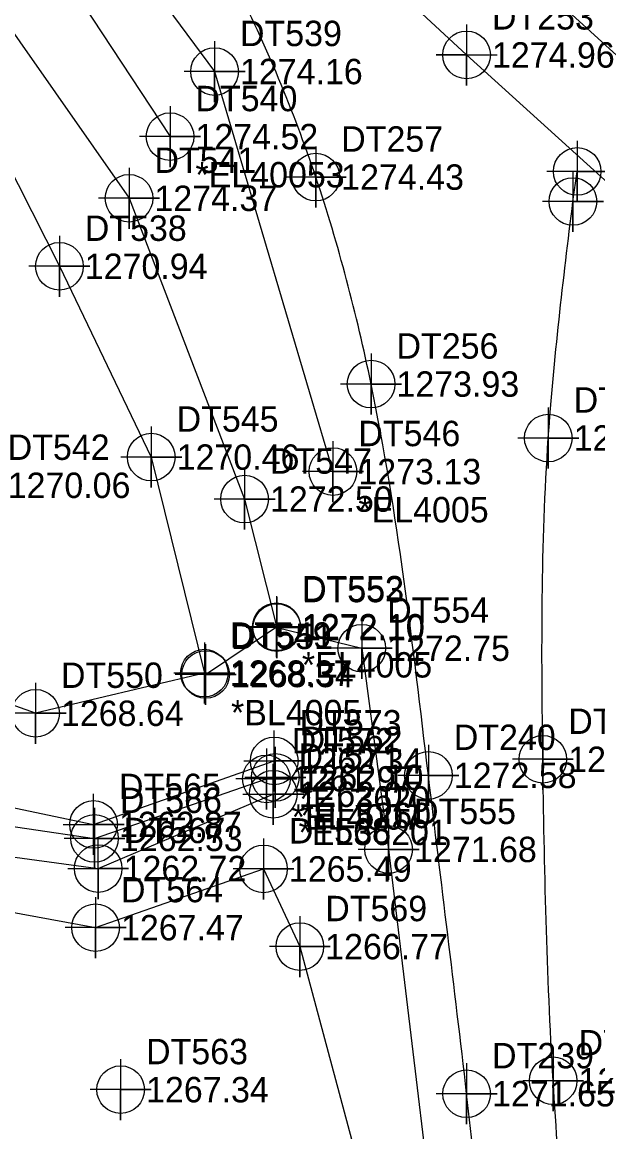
# Model space of a CAD drawing. Extents: x 1391270 to 1392151, y 960049 to 960667.
# Drawn here: x 1391450.5 to 1391507.1, y 960335.6 to 960444.8 of the extents above; entities that cross this region are included whole.
import ezdxf

# ---------------------------------------------------------------- set-up
doc = ezdxf.new("R2010")
doc.units = 0
for name, color, linetype in [('Exist DTM Breakline', 7, 'Continuous'), ('Exist DTM Breakline Cogo Comment', 7, 'Continuous'), ('Exist DTM Breakline Cogo Elevation', 7, 'Continuous'), ('Exist DTM Breakline Cogo Number', 7, 'Continuous'), ('Exist DTM Breakline Cogo Point CELL', 7, 'Continuous'), ('Exist DTM Breakline Underwater', 7, 'Continuous'), ('Exist DTM Breakline Underwater Cogo Comment', 7, 'Continuous'), ('Exist DTM Breakline Underwater Cogo Elevation', 7, 'Continuous'), ('Exist DTM Breakline Underwater Cogo Number', 7, 'Continuous'), ('Exist DTM Breakline Underwater Cogo Point CELL', 7, 'Continuous'), ('Exist DTM Crownline', 7, 'Continuous'), ('Exist DTM Crownline Cogo Elevation', 7, 'Continuous'), ('Exist DTM Crownline Cogo Number', 7, 'Continuous'), ('Exist DTM Crownline Cogo Point CELL', 7, 'Continuous'), ('Exist DTM Regular Point CELL', 7, 'Continuous'), ('Exist DTM Regular Point Cogo Elevation', 7, 'Continuous'), ('Exist DTM Regular Point Cogo Number', 7, 'Continuous'), ('Exist Hydro Stream or Body of Water', 7, 'Continuous'), ('Exist Hydro Stream or Body of Water Cogo Comment', 7, 'Continuous'), ('Exist Hydro Stream or Body of Water Cogo Elevation', 7, 'Continuous'), ('Exist Hydro Stream or Body of Water Cogo Number', 7, 'Continuous'), ('Exist Hydro Stream or Body of Water Cogo Point CELL', 7, 'Continuous'), ('Exist Roads EOP', 7, 'Continuous'), ('Exist Roads EOP Cogo Elevation', 7, 'Continuous'), ('Exist Roads EOP Cogo Number', 7, 'Continuous'), ('Exist Roads EOP Cogo Point CELL', 7, 'Continuous'), ('Exist Roads EOT', 7, 'Continuous'), ('Exist Roads EOT Cogo Elevation', 7, 'Continuous'), ('Exist Roads EOT Cogo Number', 7, 'Continuous'), ('Exist Roads EOT Cogo Point CELL', 7, 'Continuous'), ('Exist Structure Minor Pipes CMP 60 Inch Cogo Comment', 7, 'Continuous'), ('Exist Structure Minor Pipes CMP 60 Inch Cogo Elevation', 7, 'Continuous'), ('Exist Structure Minor Pipes CMP 60 Inch Cogo Number', 7, 'Continuous'), ('Exist Structure Minor Pipes CMP 60 Inch Cogo Point CELL', 7, 'Continuous')]:
    doc.layers.add(name, color=color, linetype=linetype)

msp = doc.modelspace()

# ---------------------------------------------------------------- linework, layer by layer
at = {"layer": 'Exist DTM Breakline'}
msp.add_line((1391468.506, 960380.602), (1391475.48, 960385.301), dxfattribs=at)
for points in [[(1391324.233, 960586.705), (1391339.042, 960571.952), (1391361.254, 960553.328), (1391397.359, 960520.55), (1391431.984, 960487.022), (1391447.858, 960468.977), (1391469.387, 960439.951), (1391481.042, 960400.574)], [(1391316.128, 960578.463), (1391335.373, 960567.825), (1391355.688, 960547.259), (1391385.482, 960507.01), (1391423.359, 960476.875), (1391439.432, 960458.285), (1391460.969, 960427.473), (1391472.339, 960397.865), (1391475.509, 960385.212), (1391483.88, 960383.187), (1391486.523, 960363.38), (1391492.773, 960311.276)], [(1391303.798, 960568.714), (1391337.195, 960549.348), (1391355.915, 960524.922), (1391369.834, 960491.808), (1391382.04, 960457.756), (1391381.24, 960442.404), (1391402.896, 960452.148), (1391420.738, 960472.565), (1391439.191, 960450.264), (1391454.114, 960420.78), (1391463.153, 960401.998), (1391468.38, 960380.734), (1391451.764, 960376.78), (1391432.731, 960383.561)], [(1391374.906, 960532.045), (1391391.307, 960515.216), (1391429.365, 960483.152), (1391444, 960465.435), (1391465.005, 960433.545)], [(1391421.76, 960362.297), (1391457.674, 960355.681), (1391474.205, 960361.463), (1391477.78, 960353.817), (1391489.16, 960311.358)]]:
    msp.add_lwpolyline(points, dxfattribs=at)
at = {"layer": 'Exist DTM Breakline Cogo Point CELL'}
for points in [[(1391469.387, 960442.951), (1391469.387, 960436.951), (1391469.387, 960439.951), (1391472.387, 960439.951), (1391466.387, 960439.951)], [(1391465.005, 960436.545), (1391465.005, 960430.545), (1391465.005, 960433.545), (1391468.005, 960433.545), (1391462.005, 960433.545)], [(1391460.969, 960430.473), (1391460.969, 960424.473), (1391460.969, 960427.473), (1391463.969, 960427.473), (1391457.969, 960427.473)], [(1391454.114, 960423.78), (1391454.114, 960417.78), (1391454.114, 960420.78), (1391457.114, 960420.78), (1391451.114, 960420.78)], [(1391463.153, 960404.998), (1391463.153, 960398.998), (1391463.153, 960401.998), (1391466.153, 960401.998), (1391460.153, 960401.998)], [(1391481.042, 960403.574), (1391481.042, 960397.574), (1391481.042, 960400.574), (1391484.042, 960400.574), (1391478.042, 960400.574)], [(1391472.339, 960400.865), (1391472.339, 960394.865), (1391472.339, 960397.865), (1391475.339, 960397.865), (1391469.339, 960397.865)], [(1391475.48, 960388.301), (1391475.48, 960382.301), (1391475.48, 960385.301), (1391478.48, 960385.301), (1391472.48, 960385.301)], [(1391475.509, 960388.212), (1391475.509, 960382.212), (1391475.509, 960385.212), (1391478.509, 960385.212), (1391472.509, 960385.212)], [(1391483.88, 960386.187), (1391483.88, 960380.187), (1391483.88, 960383.187), (1391486.88, 960383.187), (1391480.88, 960383.187)], [(1391468.38, 960383.734), (1391468.38, 960377.734), (1391468.38, 960380.734), (1391471.38, 960380.734), (1391465.38, 960380.734)], [(1391468.506, 960383.602), (1391468.506, 960377.602), (1391468.506, 960380.602), (1391471.506, 960380.602), (1391465.506, 960380.602)], [(1391451.764, 960379.78), (1391451.764, 960373.78), (1391451.764, 960376.78), (1391454.764, 960376.78), (1391448.764, 960376.78)], [(1391486.523, 960366.38), (1391486.523, 960360.38), (1391486.523, 960363.38), (1391489.523, 960363.38), (1391483.523, 960363.38)], [(1391474.205, 960364.463), (1391474.205, 960358.463), (1391474.205, 960361.463), (1391477.205, 960361.463), (1391471.205, 960361.463)], [(1391457.674, 960358.681), (1391457.674, 960352.681), (1391457.674, 960355.681), (1391460.674, 960355.681), (1391454.674, 960355.681)], [(1391477.78, 960356.817), (1391477.78, 960350.817), (1391477.78, 960353.817), (1391480.78, 960353.817), (1391474.78, 960353.817)]]:
    msp.add_lwpolyline(points, dxfattribs=at)
for centre in [(1391469.387, 960439.951), (1391465.005, 960433.545), (1391460.969, 960427.473), (1391454.114, 960420.78), (1391463.153, 960401.998), (1391481.042, 960400.574), (1391472.339, 960397.865), (1391475.48, 960385.301), (1391475.509, 960385.212), (1391483.88, 960383.187), (1391468.38, 960380.734), (1391468.506, 960380.602), (1391451.764, 960376.78), (1391486.523, 960363.38), (1391474.205, 960361.463), (1391457.674, 960355.681), (1391477.78, 960353.817)]:
    msp.add_circle(centre, 2.344, dxfattribs=at)
at = {"layer": 'Exist DTM Breakline Underwater'}
msp.add_lwpolyline([(1391424.242, 960369.381), (1391457.57, 960364.468), (1391474.484, 960370.327)], dxfattribs=at)
at = {"layer": 'Exist DTM Breakline Underwater Cogo Point CELL'}
for points in [[(1391474.484, 960373.327), (1391474.484, 960367.327), (1391474.484, 960370.327), (1391477.484, 960370.327), (1391471.484, 960370.327)], [(1391457.57, 960367.468), (1391457.57, 960361.468), (1391457.57, 960364.468), (1391460.57, 960364.468), (1391454.57, 960364.468)]]:
    msp.add_lwpolyline(points, dxfattribs=at)
for centre in [(1391474.484, 960370.327), (1391457.57, 960364.468)]:
    msp.add_circle(centre, 2.344, dxfattribs=at)
at = {"layer": 'Exist DTM Crownline'}
msp.add_line((1391504.663, 960427.16), (1391505.082, 960430.114), dxfattribs=at)
msp.add_lwpolyline([(1391336.775, 960598.787), (1391373.255, 960565.397), (1391410.328, 960531.742), (1391446.425, 960498.79), (1391483.147, 960465.095), (1391520.03, 960431.473), (1391553.996, 960400.745), (1391556.572, 960398.448)], dxfattribs=at)
msp.add_spline([(1391505.005, 960312.528), (1391502.717, 960340.608), (1391501.701, 960372.252), (1391502.238, 960403.877), (1391504.663, 960427.16)], degree=3, dxfattribs=at)
at = {"layer": 'Exist DTM Crownline Cogo Point CELL'}
for points in [[(1391505.082, 960433.114), (1391505.082, 960427.114), (1391505.082, 960430.114), (1391508.082, 960430.114), (1391502.082, 960430.114)], [(1391504.663, 960430.16), (1391504.663, 960424.16), (1391504.663, 960427.16), (1391507.663, 960427.16), (1391501.663, 960427.16)], [(1391502.238, 960406.877), (1391502.238, 960400.877), (1391502.238, 960403.877), (1391505.238, 960403.877), (1391499.238, 960403.877)], [(1391501.701, 960375.252), (1391501.701, 960369.252), (1391501.701, 960372.252), (1391504.701, 960372.252), (1391498.701, 960372.252)], [(1391502.717, 960343.608), (1391502.717, 960337.608), (1391502.717, 960340.608), (1391505.717, 960340.608), (1391499.717, 960340.608)]]:
    msp.add_lwpolyline(points, dxfattribs=at)
for centre in [(1391505.082, 960430.114), (1391504.663, 960427.16), (1391502.238, 960403.877), (1391501.701, 960372.252), (1391502.717, 960340.608)]:
    msp.add_circle(centre, 2.344, dxfattribs=at)
at = {"layer": 'Exist DTM Regular Point CELL'}
msp.add_lwpolyline([(1391460.143, 960342.737), (1391460.143, 960336.737), (1391460.143, 960339.737), (1391463.143, 960339.737), (1391457.143, 960339.737)], dxfattribs=at)
msp.add_circle((1391460.143, 960339.737), 2.344, dxfattribs=at)
at = {"layer": 'Exist Hydro Stream or Body of Water'}
for points in [[(1391424.856, 960372.683), (1391457.478, 960365.839), (1391475.256, 960372.097)], [(1391423.375, 960366.208), (1391457.93, 960361.502), (1391475.159, 960368.812)]]:
    msp.add_lwpolyline(points, dxfattribs=at)
at = {"layer": 'Exist Hydro Stream or Body of Water Cogo Point CELL'}
for points in [[(1391472.256, 960372.097), (1391478.256, 960372.097), (1391475.256, 960372.097), (1391475.256, 960369.097), (1391475.256, 960375.097)], [(1391472.159, 960368.812), (1391478.159, 960368.812), (1391475.159, 960368.812), (1391475.159, 960365.812), (1391475.159, 960371.812)], [(1391454.478, 960365.839), (1391460.478, 960365.839), (1391457.478, 960365.839), (1391457.478, 960362.839), (1391457.478, 960368.839)], [(1391454.93, 960361.502), (1391460.93, 960361.502), (1391457.93, 960361.502), (1391457.93, 960358.502), (1391457.93, 960364.502)]]:
    msp.add_lwpolyline(points, dxfattribs=at)
for centre in [(1391475.256, 960372.097), (1391475.159, 960368.812), (1391457.478, 960365.839), (1391457.93, 960361.502)]:
    msp.add_circle(centre, 2.344, dxfattribs=at)
at = {"layer": 'Exist Roads EOP'}
for points in [[(1391558.507, 960409.653), (1391527.113, 960438.384), (1391489.556, 960472.216), (1391453.007, 960506.097), (1391416.783, 960539.246), (1391379.565, 960572.597), (1391343.959, 960605.485)], [(1391497.16, 960311.857), (1391494.199, 960339.333), (1391490.437, 960370.67), (1391484.795, 960409.189), (1391479.352, 960429.561), (1391471.345, 960448.702), (1391460.843, 960466.873), (1391449.093, 960483.056), (1391440.139, 960491.898), (1391403.899, 960524.912), (1391366.94, 960558.603)]]:
    msp.add_spline(points, degree=3, dxfattribs=at)
at = {"layer": 'Exist Roads EOP Cogo Point CELL'}
for points in [[(1391479.352, 960432.561), (1391479.352, 960426.561), (1391479.352, 960429.561), (1391482.352, 960429.561), (1391476.352, 960429.561)], [(1391484.795, 960412.189), (1391484.795, 960406.189), (1391484.795, 960409.189), (1391487.795, 960409.189), (1391481.795, 960409.189)], [(1391490.437, 960373.67), (1391490.437, 960367.67), (1391490.437, 960370.67), (1391493.437, 960370.67), (1391487.437, 960370.67)], [(1391494.199, 960342.333), (1391494.199, 960336.333), (1391494.199, 960339.333), (1391497.199, 960339.333), (1391491.199, 960339.333)]]:
    msp.add_lwpolyline(points, dxfattribs=at)
for centre in [(1391479.352, 960429.561), (1391484.795, 960409.189), (1391490.437, 960370.67), (1391494.199, 960339.333)]:
    msp.add_circle(centre, 2.344, dxfattribs=at)
at = {"layer": 'Exist Roads EOT'}
msp.add_lwpolyline([(1391542.319, 960398.059), (1391518.576, 960419.517), (1391494.192, 960441.585), (1391465.739, 960467.932), (1391455.599, 960477.451)], dxfattribs=at)
at = {"layer": 'Exist Roads EOT Cogo Point CELL'}
msp.add_lwpolyline([(1391494.192, 960444.585), (1391494.192, 960438.585), (1391494.192, 960441.585), (1391491.192, 960441.585), (1391497.192, 960441.585)], dxfattribs=at)
msp.add_circle((1391494.192, 960441.585), 2.344, dxfattribs=at)
at = {"layer": 'Exist Structure Minor Pipes CMP 60 Inch Cogo Point CELL'}
msp.add_lwpolyline([(1391475.363, 960373.472), (1391475.363, 960367.472), (1391475.363, 960370.472), (1391478.363, 960370.472), (1391472.363, 960370.472)], dxfattribs=at)
msp.add_circle((1391475.363, 960370.472), 2.344, dxfattribs=at)

# ---------------------------------------------------------------- texts
at = {"layer": 'Exist DTM Breakline Cogo Comment'}
for s, p in [('*EL40053', (1391467.505, 960428.545)), ('*EL4005', (1391483.542, 960395.574)), ('*EL4005', (1391477.98, 960380.301)), ('*BL4005', (1391471.006, 960375.602))]:
    msp.add_text(s, height=2.5, dxfattribs=at).set_placement(p)
at = {"layer": 'Exist DTM Breakline Cogo Elevation'}
for s, p in [('1274.16', (1391471.887, 960438.701)), ('1274.52', (1391467.505, 960432.295)), ('1274.37', (1391463.469, 960426.223)), ('1270.94', (1391456.614, 960419.53)), ('1270.46', (1391465.653, 960400.748)), ('1273.13', (1391483.542, 960399.324)), ('1272.50', (1391474.839, 960396.615)), ('1272.10', (1391477.98, 960384.051)), ('1272.10', (1391478.009, 960383.962)), ('1272.75', (1391486.38, 960381.937)), ('1268.37', (1391470.88, 960379.484)), ('1268.34', (1391471.006, 960379.352)), ('1268.64', (1391454.264, 960375.53)), ('1271.68', (1391489.023, 960362.13)), ('1265.49', (1391476.705, 960360.213)), ('1267.47', (1391460.174, 960354.431)), ('1266.77', (1391480.28, 960352.567))]:
    msp.add_text(s, height=2.5, dxfattribs=at).set_placement(p)
at = {"layer": 'Exist DTM Breakline Cogo Number'}
for s, p in [('DT539', (1391471.887, 960442.451)), ('DT540', (1391467.505, 960436.045)), ('DT541', (1391463.469, 960429.973)), ('DT538', (1391456.614, 960423.28)), ('DT545', (1391465.653, 960404.498)), ('DT546', (1391483.542, 960403.074)), ('DT547', (1391474.839, 960400.365)), ('DT552', (1391477.98, 960387.801)), ('DT553', (1391478.009, 960387.712)), ('DT554', (1391486.38, 960385.687)), ('DT549', (1391470.88, 960383.234)), ('DT551', (1391471.006, 960383.102)), ('DT550', (1391454.264, 960379.28)), ('DT555', (1391489.023, 960365.88)), ('DT568', (1391476.705, 960363.963)), ('DT564', (1391460.174, 960358.181)), ('DT569', (1391480.28, 960356.317))]:
    msp.add_text(s, height=2.5, dxfattribs=at).set_placement(p)
at = {"layer": 'Exist DTM Breakline Underwater Cogo Comment'}
msp.add_text('*EL4007', height=2.5, dxfattribs=at).set_placement((1391476.984, 960365.327))
at = {"layer": 'Exist DTM Breakline Underwater Cogo Elevation'}
for s, p in [('1261.97', (1391476.984, 960369.077)), ('1262.53', (1391460.07, 960363.218))]:
    msp.add_text(s, height=2.5, dxfattribs=at).set_placement(p)
at = {"layer": 'Exist DTM Breakline Underwater Cogo Number'}
for s, p in [('DT572', (1391476.984, 960372.827)), ('DT566', (1391460.07, 960366.968))]:
    msp.add_text(s, height=2.5, dxfattribs=at).set_placement(p)
at = {"layer": 'Exist DTM Crownline Cogo Elevation'}
for s, p in [('1273.89', (1391504.738, 960402.627)), ('1272.77', (1391504.201, 960371.002)), ('1271.88', (1391505.217, 960339.358))]:
    msp.add_text(s, height=2.5, dxfattribs=at).set_placement(p)
at = {"layer": 'Exist DTM Crownline Cogo Number'}
for s, p in [('DT242', (1391504.738, 960406.377)), ('DT241', (1391504.201, 960374.752)), ('DT238', (1391505.217, 960343.108))]:
    msp.add_text(s, height=2.5, dxfattribs=at).set_placement(p)
at = {"layer": 'Exist DTM Regular Point Cogo Elevation'}
for s, p in [('1270.06', (1391449.022, 960397.973)), ('1267.34', (1391462.643, 960338.487))]:
    msp.add_text(s, height=2.5, dxfattribs=at).set_placement(p)
at = {"layer": 'Exist DTM Regular Point Cogo Number'}
for s, p in [('DT542', (1391449.022, 960401.723)), ('DT563', (1391462.643, 960342.237))]:
    msp.add_text(s, height=2.5, dxfattribs=at).set_placement(p)
at = {"layer": 'Exist Hydro Stream or Body of Water Cogo Comment'}
for s, p in [('*EL3620', (1391477.756, 960367.097)), ('*EL36201', (1391477.659, 960363.812))]:
    msp.add_text(s, height=2.5, dxfattribs=at).set_placement(p)
at = {"layer": 'Exist Hydro Stream or Body of Water Cogo Elevation'}
for s, p in [('1262.34', (1391477.756, 960370.847)), ('1262.07', (1391477.659, 960367.562)), ('1262.87', (1391459.978, 960364.589)), ('1262.72', (1391460.43, 960360.252))]:
    msp.add_text(s, height=2.5, dxfattribs=at).set_placement(p)
at = {"layer": 'Exist Hydro Stream or Body of Water Cogo Number'}
for s, p in [('DT573', (1391477.756, 960374.597)), ('DT571', (1391477.659, 960371.312)), ('DT565', (1391459.978, 960368.339)), ('DT567', (1391460.43, 960364.002))]:
    msp.add_text(s, height=2.5, dxfattribs=at).set_placement(p)
at = {"layer": 'Exist Roads EOP Cogo Elevation'}
for s, p in [('1274.43', (1391481.852, 960428.311)), ('1273.93', (1391487.295, 960407.939)), ('1272.58', (1391492.937, 960369.42)), ('1271.65', (1391496.699, 960338.083))]:
    msp.add_text(s, height=2.5, dxfattribs=at).set_placement(p)
at = {"layer": 'Exist Roads EOP Cogo Number'}
for s, p in [('DT257', (1391481.852, 960432.061)), ('DT256', (1391487.295, 960411.689)), ('DT240', (1391492.937, 960373.17)), ('DT239', (1391496.699, 960341.833))]:
    msp.add_text(s, height=2.5, dxfattribs=at).set_placement(p)
at = {"layer": 'Exist Roads EOT Cogo Elevation'}
msp.add_text('1274.96', height=2.5, dxfattribs=at).set_placement((1391496.692, 960440.335))
at = {"layer": 'Exist Roads EOT Cogo Number'}
msp.add_text('DT253', height=2.5, dxfattribs=at).set_placement((1391496.692, 960444.085))
at = {"layer": 'Exist Structure Minor Pipes CMP 60 Inch Cogo Comment'}
msp.add_text('*EL5260', height=2.5, dxfattribs=at).set_placement((1391477.863, 960365.472))
at = {"layer": 'Exist Structure Minor Pipes CMP 60 Inch Cogo Elevation'}
msp.add_text('1262.10', height=2.5, dxfattribs=at).set_placement((1391477.863, 960369.222))
at = {"layer": 'Exist Structure Minor Pipes CMP 60 Inch Cogo Number'}
msp.add_text('DT562', height=2.5, dxfattribs=at).set_placement((1391477.863, 960372.972))

doc.saveas('drawing.dxf')
